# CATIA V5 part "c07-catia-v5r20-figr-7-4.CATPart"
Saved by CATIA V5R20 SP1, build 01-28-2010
Part number: Part1
Bounding box of the stored display mesh (mm): x -20 to 20, y -95 to 0, z 0 to 40
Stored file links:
  D:\v5_r20\psrt_files_downloaded\c07-catia-v5r20-prt\c07-catia-v5r20-figr-7-4.CATPart
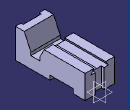
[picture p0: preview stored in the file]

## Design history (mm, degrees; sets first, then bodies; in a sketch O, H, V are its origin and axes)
Body1 (main body)
  Sketch1 on yz-plane, origin (0, 0, 0), H (0, 1, 0), V (0, 0, 1)
    line L1 (0, 0) -> (-16, 0)
    line L2 (-16, 0) -> (-16, 6)
    line L3 (-16, 6) -> (-48, 6)
    line L4 (-48, 6) -> (-48, 0)
    point P4 (-48, 0)
    line L5 (-48, 0) -> (-95, 0)
    line L6 (-95, 0) -> (-95, 40)
    line L7 (-95, 40) -> (-83, 40)
    line L8 (-83, 40) -> (-74, 20)
    line L9 (-74, 20) -> (-74, 16)
    line L10 (-74, 16) -> (-62, 16)
    line L11 (-62, 16) -> (-62, 20)
    line L12 (-62, 20) -> (-56, 32)
    line L13 (-56, 32) -> (0, 32)
    line L14 (0, 32) -> (0, 0)
    length L1 = 16
    length L3 = 32
    length L13 = 56
    distance L14 L6 = 95
    length L14 = 32
    length L6 = 40
    length L12 H = 6
    length L10 = 12
    length L7 = 12
    length L9 = 4
    length L2 = 6
    distance L10 L5 = 16
    length L12 V = 12
    horizontal: L1 H, L3 H, L5 H, L7 H, L10 H, L13 H
    vertical: L2 V, L4 V, L6 V, L9 V, L11 V, L14 V
    coincidence: P4 H
  Pad1: profile Sketch1, direction (1, 0, 0), length 20, mirrored extent
  Sketch2 on face of Pad1, origin (0, 0, 0), H (-1, 0, 0), V (0, 0, 1)
    axis line L1 (0, 0) -> (0, 40.9766)
    point P2 (0, 32)
    line L2 (0, 32) -> (-8, 32)
    point P3 (-8, 32)
    line L3 (-8, 32) -> (-12, 26)
    point P4 (-12, 26)
    line L4 (-12, 26) -> (0, 26)
    point P5 (0, 26)
    reference projected line E1 (-20, 32) -> (20, 32) from edge [face of Pad1 | face of Pad1]
    point P6 (0, 32)
    point P7 (8, 32)
    point P8 (12, 26)
    point P9 (0, 26)
    line L5 (0, 32) -> (8, 32)
    line L6 (8, 32) -> (12, 26)
    line L7 (12, 26) -> (0, 26)
    reference projected line E2 (-20, 0) -> (-20, 32) from edge [face of Pad1 | face of Pad1]
    reference projected line E3 (-20, 20) -> (-20, 40) from edge [face of Pad1 | face of Pad1]
    distance P4 E2 = 8
    length L3 V = 6
    distance P3 E3 = 12
    vertical: L1 V
    coincidence: P2 L1, P5 L1, L2 E1, P2 P6, P5 P9
    horizontal: L2 H, L4 H
    symmetry: P2 P6 L1, P3 P7 L1, P4 P8 L1, P5 P9 L1, L2 L5 L1, L3 L6 L1, L4 L7 L1
  Pocket1: profile Sketch2, direction (0, -1, 0), through (limit type 6)
  Sketch3 on face of Pad1, origin (0, 0, 0), H (-1, 0, 0), V (0, 0, 1)
    line L1 (-6, 0) -> (6, 0)
    line L2 (6, 0) -> (6, 26)
    line L3 (6, 26) -> (-6, 26)
    line L4 (-6, 26) -> (-6, 0)
    reference projected line E1 (-12, 26) -> (0, 26) from edge [face of Pad1 | face of Pocket1]
    length L1 = 12
    horizontal: L1 H, L3 H
    vertical: L2 V, L4 V
    midpoint: O L1
    coincidence: L3 E1
  Pocket2: profile Sketch3, direction (0, -1, 0), length 4
  Sketch4 "Sketch.4" on face of Pad1, origin (0, 0, 40), H (1, 0, 0), V (0, 1, 0)
    line L1 (-12.5, -95) -> (12.5, -95)
    line L2 (12.5, -95) -> (12.5, -92)
    line L3 (12.5, -92) -> (-12.5, -92)
    line L4 (-12.5, -92) -> (-12.5, -95)
    reference projected line E1 (-20, -95) -> (20, -95) from edge [face of Pad1 | face of Pad1]
    axis line L5 (0, 0) -> (0, -95)
    point P5 (0, -95)
    length L1 = 25
    length L2 = 3
    horizontal: L1 H, L3 H
    vertical: L2 V, L4 V, L5 V
    coincidence: L1 E1
    midpoint: P5 L1
  Pocket3 "Pocket.3": profile Sketch4, direction (0, 0, -1), through (limit type 3)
